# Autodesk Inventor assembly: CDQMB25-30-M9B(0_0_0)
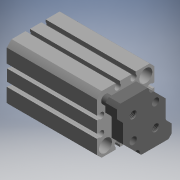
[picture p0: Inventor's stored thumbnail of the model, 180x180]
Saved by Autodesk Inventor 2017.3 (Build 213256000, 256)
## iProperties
Category: PARTsolutions
Part Number: CDQMB25-30-M9B(0_0_0)
Catalog Web Link: www.cadenas.de
Description: CQM/CDQM-Compact Cylinder Guide Rod Type
Document SubType Name: Assembly
Designer: partserver
Mass: 83.8507 g
Surface Area: 351.278 cm^2
Volume: 83.8507 cm^3
Density: 1 g/cm^3
Title: CDQMB25-30-M9B
Author: Cadenas PARTsolutions
Comments: Compact Cylinder Guide Rod Type
PSOL_IDENT_0: {$CADENAS_DATA\23d-libs\smc_jp\actuator\compact_cylinder\cqm\cqm_asmtab.prj},262 {VTYP=3D},{STYP=ASS
PSOL_IDENT_1: TAB},{NB=CDQMB25-30-M9B(0_0_0)},{LINA=CDQMB25-30-M9B},{NN=CQM/CDQM},{DATE=09.12.2020 02:52:30},{GEOM
PSOL_IDENT_2: DATE=26.03.2020 06:55:43},{VERSION=},{LINEID=40},{WBVAR=MAGNET,THREAD1,AUTOSWITCH,LEAD,NUMBER,STROKE
PSOL_IDENT_3: ,POS,STOP,THREAD2},{WBNUMERIC=STROKE,POS}  {NB=CDQMB25-30-M9B(0_0_0)},{LINA=CDQMB25-30-M9B},{KT=DUMM
PSOL_IDENT_4: Y},{BORE=25},{TIF=A},{MOUNT=(B) Through-hole/Both ends tapped (Standard)},{MOUNTX=B},{MAGNET=D},{THR
PSOL_IDENT_5: EAD1=},{THREAD1X='','(-) M thread'},{AUTOSWITCH=-M9B},{AUTOSWITCHX='','(-) Without autoswitch','-M9N
PSOL_IDENT_6: V','M9NV', '-M9PV', 'M9PV', '-M9BV', 'M9BV','-M9NWV', 'M9NWV', '-M9PWV', 'M9PWV', '-M9BWV', 'M9BWV',
PSOL_IDENT_7: '-A96V', 'A96V', '-A93V', 'A93V', '-A90V', 'A90V', '-M9N', 'M9N', '-M9P', 'M9P', '-M9B', 'M9B', '-M
PSOL_IDENT_8: 9NW', 'M9NW', '-M9PW', 'M9PW', '-M9BW', 'M9BW', '-A96', 'A96','-A93', 'A93', '-A90', 'A90', '-M9NAV'
PSOL_IDENT_9: , 'M9NAV', '-M9PAV', 'M9PAV', '-M9BAV', 'M9BAV', '-M9NA', 'M9NA', '-M9PA','M9PA', '-M9BA', 'M9BA'},{
PSOL_IDENT_10: LEAD=},{LEADX='','(-) 0.5 m', 'M','(M) 1 m' , 'L','(L) 3 m' , 'Z','(Z) 5 m' },{NUMBER=},{NUMBERX='',
PSOL_IDENT_11: '(-) 2 pcs', 'S', '(S) 1 pc'},{STROKE=30},{STROKEX=[15:50/5]},{POS=0},{SMAX=50},{SMINX=15},{SMIN=15
PSOL_IDENT_12: },{STOP=0},{COM=-},{THREAD2=0},{ORDER=CDQMB25-30-M9B},{A=45.5},{A1=35.5},{A2=45.5},{B=32.5},{B1=22.5
PSOL_IDENT_13: },{B2=32.5},{EA=40},{EB=38},{EC=0.0},{F=5.5},{F1=5.5},{HA=M5x0.8},{OA=M6x1.0},{HB=5 +0.2/0},{IA=52},
PSOL_IDENT_14: {IB=50.5},{J=0.0},{KA=22 +0.1/-0.1},{KB=15.6},{L=5.0},{M=28.0},{N=5.4},{OB=9.0},{Q=11.0},{Q1=11.0},{
PSOL_IDENT_15: RA=10},{RB=7.0},{T=1.0},{V=30.0},{W=8},{Z=0},{PP=M5x0.8},{PTN=-},{PTF=-},{P=M5x0.8},{PPATH=assembly/
PSOL_IDENT_16: cqm_asmsbl.prj},{MODEL=CDQMB25-30-M9B},{NENN=CDQMB25}
NB: CDQMB25-30-M9B(0_0_0)
NN: CQM/CDQM
NT: Compact Cylinder Guide Rod Type
NBSYN: $ORDER.($POS._$STOP._$THREAD2.)
LINA: CDQMB25-30-M9B
CATALOG: SMC (JP
ROWDESC: CDQMB25
BORE: 25
MOUNT: (B) Through-hole/Both ends tapped (Standard)
MAGNET: (D) With magnet
THREAD1: (-) M thread
AUTOSWITCH: M9B Solid state-General-Grommet-Indicator light:Yes-2 wire-In line
LEAD: (-) 0.5 m
NUMBER: (-) 2 pcs
STROKE: 30
POS: 0
STOP: Standard stroke
COM: -
THREAD2: on
ARTICLENO: CDQMB25-30-M9B(0_0_0)
BOMINFO: CDQMB25-30-M9B
CREATOR: CADENAS GmbH
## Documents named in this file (4)
- e:\temp\worker_18\temp\exporttempdir_4580_20_Ls4wZ\format_0\CDQMB25-30-M9B(0_0_0).iam
- e:\temp\worker_18\temp\exporttempdir_4580_20_Ls4wZ\format_0\CDQMB25-30-M9B(0)_BODY.ipt
- e:\temp\worker_18\temp\exporttempdir_4580_20_Ls4wZ\format_0\CDQMB25-30(0)_ROD.ipt
- e:\temp\worker_18\temp\exporttempdir_4580_20_Ls4wZ\format_0\CQM-M9B.ipt
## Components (4 placed, 3 different names)
1. CDQMB25-30-M9B(0)_BODY:1
2. CDQMB25-30(0)_ROD:1
3. CQM-M9B:1
4. CQM-M9B:2
